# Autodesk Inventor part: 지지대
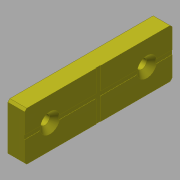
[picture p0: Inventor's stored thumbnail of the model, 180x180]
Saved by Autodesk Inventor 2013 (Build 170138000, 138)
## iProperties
Created: 2017-04
Part Number: 지지대
Material: 강철
Document SubType Name: Modeling
Designer: mduedu
Density: 1 g/cm^3
Author: mduedu
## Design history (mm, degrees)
sketch "스케치1"
  geometry: L1 (23, -35)-(23, 35); L2 (0, -35)-(0, 35); L3 (0, 35)-(23, 35); L4 (0, -35)-(23, -35); 2 further points
  constraints: 8 end point, 2 parallel, 1 coincident, 1 midpoint, 1 perpendicular, 1 vertical
  dimensions: "d1" = 23 distance between parallel lines of L2 L1; "d15" = 70 distance of L1.start L1.end
extrude "돌출1" new body sketch "스케치1" distance "d2" = 8; taper "d3" = 0 deg
chamfer "모따기2" distance "d16" = 1; stored, may be unused: second distance "d17" = 2, angle "d18" = 45 deg
sketch "스케치2"
  geometry: L1 (1, -35)-(22, -35) reference; L2 (23, -34)-(23, 34) reference; L3 (22, 35)-(1, 35) reference; L4 (0, 34)-(0, -34) reference; L5 (11.5, 35)-(11.5, -35); L6 (23, 0)-(0, 0); L7 (1, -35)-(0, -34) reference; L8 (23, -34)-(22, -35) reference; L9 (22, 35)-(23, 34) reference; L10 (0, 34)-(1, 35) reference; 2 further points
  constraints: 4 end point, 4 midpoint, 1 point on line, 1 symmetric about line
  dimensions: "d7" = 12 distance from line of point (11.5, 23) L3
  node "투영된 루프1"
sketch "스케치3"
  geometry: 4 further points
  constraints: 2 coincident
hole "구멍1" sketch "스케치3" at (11.5, 23), (11.5, -23) diameter "d8" = 4.5; stored, may be unused: countersink angle "d12" = 90 deg, drill point angle "d14" = 0 deg; dims "d9" = 6, "d10" = 9.4, "d11" = 2, "d13" = 8
sketch "스케치4"
  geometry: L1 (-35, 22)-(-35, 1) reference; L2 (35, 1)-(35, 22) reference; L3 (34, 23)-(-34, 23) reference; L4 (-34, 0)-(34, 0) reference; L5 (-35, 11.5)-(35, 11.5); L6 (0, 23)-(0, 0); L7 (-35, 12.5)-(35, 12.5); L8 (-35, 10.5)-(35, 10.5); L9 (-1, 23)-(-1, 0); L10 (1, 23)-(1, 0)
  constraints: 12 end point, 8 point on line, 4 parallel, 3 midpoint, 3 perpendicular
  dimensions: "d19" = 1 distance between parallel lines of L7 L5; "d21" = 1 distance between parallel lines of L8 L5; "d22" = 1 distance between parallel lines of L9 L6; "d23" = 1 distance between parallel lines of L10 L6
extrude "돌출2" cut sketch "스케치4" distance "d24" = 0.2; taper "d25" = 0 deg
extrude "돌출3" cut sketch "스케치4" distance "d26" = 0.2; taper "d27" = 0 deg
fillet "모깎기1" dims "d28" = 0.2
node "솔리드2"
node "솔리드1"
